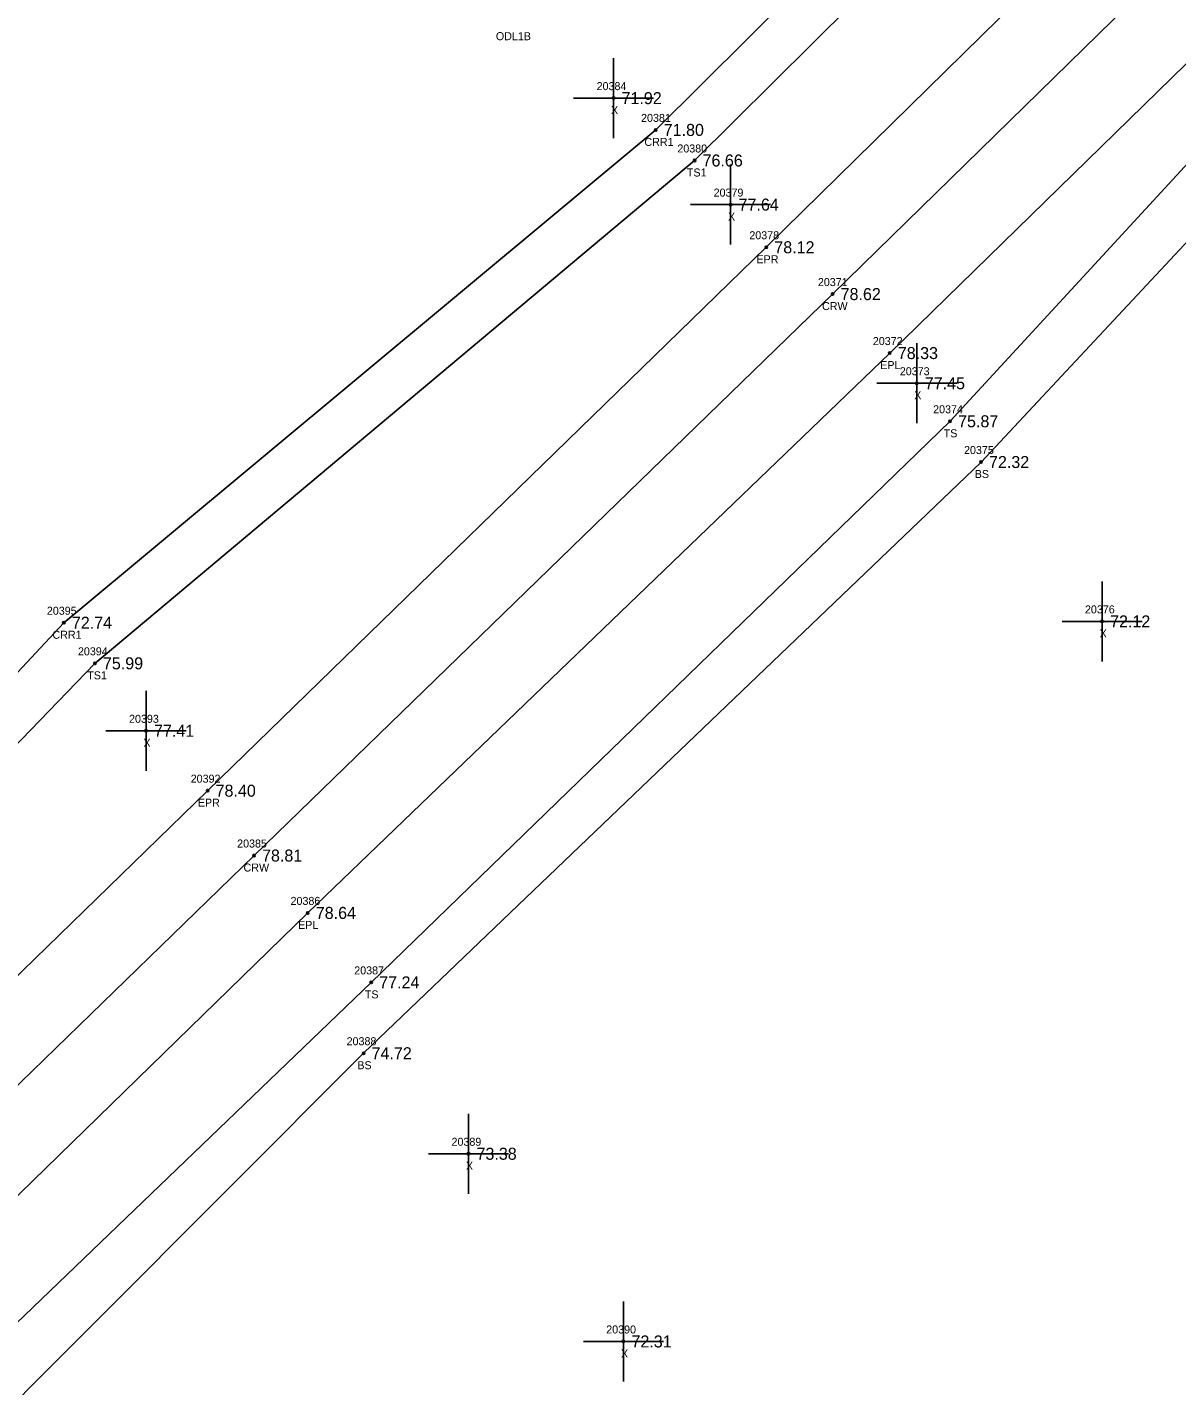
# Model space of a CAD drawing. Extents: x 2505300 to 2506184, y 912965 to 913825.
# Drawn here: x 2505409.2 to 2505552.8, y 913054.5 to 913224.2 of the extents above; entities that cross this region are included whole.
import ezdxf

# ---------------------------------------------------------------- set-up
doc = ezdxf.new("R2010")
doc.units = 0
for name, color, linetype in [('RD_DTM_BkLn1', 7, 'Continuous'), ('RD_DTM_BkLn2', 7, 'Continuous'), ('RD_DTM_BkLn_txCode', 7, 'Continuous'), ('RD_EX_H2O', 7, 'Continuous'), ('RD_EX_H2O_txCode', 7, 'Continuous'), ('RD_EX_Misc', 7, 'Continuous'), ('RD_EX_Misc_txCode', 7, 'Continuous'), ('RD_EX_Road', 7, 'Continuous'), ('RD_EX_Road_txCode', 7, 'Continuous'), ('RD_EX_TX_H2O_ELEV', 7, 'Continuous'), ('RD_EX_TX_Misc_ELEV', 7, 'Continuous'), ('RD_EX_TX_Road_ELEV', 7, 'Continuous'), ('RD_HC_Survey_ELEV', 7, 'Continuous'), ('RD_HC_Survey_txCode', 7, 'Continuous'), ('RD_SMD_Locator', 7, 'Continuous')]:
    doc.layers.add(name, color=color, linetype=linetype)

msp = doc.modelspace()

# ---------------------------------------------------------------- linework, layer by layer
at = {"layer": 'RD_DTM_BkLn1'}
msp.add_lwpolyline([(2505767.92, 913463.52), (2505733.49, 913421.6), (2505698.21, 913380.67), (2505657.08, 913336.16), (2505615.28, 913294.08), (2505578.04, 913257.66), (2505509.81, 913190.87), (2505437.56, 913120.73), (2505363.23, 913048.54)], dxfattribs=at)
at = {"layer": 'RD_DTM_BkLn2'}
for points in [[(2505753.71, 913473.94), (2505744.94, 913478.08), (2505723.86, 913460.1), (2505705.31, 913435.28), (2505675.97, 913399.31), (2505635.15, 913352.85), (2505596.03, 913310.85), (2505561.37, 913275.87), (2505492.57, 913207.56), (2505417.69, 913144.74), (2505344.31, 913068.67)], [(2505608.57, 913197.02), (2505580.09, 913207.47), (2505555.7, 913208.91), (2505524.48, 913174.98), (2505452.19, 913104.88), (2505378.2, 913033.83)], [(2505606.77, 913192.45), (2505577.32, 913200.72), (2505558.46, 913202.1), (2505528.34, 913169.89), (2505451.24, 913096.03), (2505383.47, 913028.12)]]:
    msp.add_lwpolyline(points, dxfattribs=at)
at = {"layer": 'RD_EX_H2O'}
msp.add_lwpolyline([(2505789.47, 913464.31), (2505758.18, 913486.1), (2505736.66, 913480.49), (2505719.32, 913463.86), (2505699.9, 913439.21), (2505669.03, 913402.75), (2505628.5, 913357.9), (2505593, 913316.39), (2505556.58, 913279.8), (2505487.72, 913211.38), (2505413.81, 913149.81), (2505341.31, 913072.1)], dxfattribs=at)
at = {"layer": 'RD_EX_Misc'}
for p, q in [((2505482.45, 913210.35), (2505482.45, 913220.35)), ((2505477.45, 913215.35), (2505487.45, 913215.35)), ((2505497.07, 913197.05), (2505497.07, 913207.05)), ((2505492.07, 913202.05), (2505502.07, 913202.05)), ((2505520.32, 913174.73), (2505520.32, 913184.73)), ((2505515.32, 913179.73), (2505525.32, 913179.73)), ((2505543.46, 913144.98), (2505543.46, 913154.98)), ((2505538.46, 913149.98), (2505548.46, 913149.98)), ((2505424.07, 913131.31), (2505424.07, 913141.31)), ((2505419.07, 913136.31), (2505429.07, 913136.31)), ((2505464.34, 913078.47), (2505464.34, 913088.47)), ((2505459.34, 913083.47), (2505469.34, 913083.47)), ((2505483.69, 913055.02), (2505483.69, 913065.02)), ((2505478.69, 913060.02), (2505488.69, 913060.02))]:
    msp.add_line(p, q, dxfattribs=at)
at = {"layer": 'RD_EX_Road'}
for points in [[(2505758.23, 913470.96), (2505754.11, 913462.85), (2505725.4, 913427.85), (2505690.77, 913387.11), (2505650.25, 913343.36), (2505607.72, 913300.12), (2505570.97, 913264.99), (2505501.53, 913196.72), (2505431.76, 913128.83), (2505356.25, 913055.37)], [(2505777.56, 913455.88), (2505770.31, 913449.85), (2505741, 913414.45), (2505705.55, 913374.27), (2505664.83, 913329.82), (2505624.02, 913288.23), (2505585.62, 913250.63), (2505516.95, 913183.5), (2505444.27, 913113.56), (2505370.6, 913041.78)]]:
    msp.add_lwpolyline(points, dxfattribs=at)
at = {"layer": 'RD_SMD_Locator'}
for centre in [(2505482.45, 913215.35), (2505487.72, 913211.38), (2505492.57, 913207.56), (2505497.07, 913202.05), (2505501.53, 913196.72), (2505509.81, 913190.87), (2505516.95, 913183.5), (2505520.32, 913179.73), (2505524.48, 913174.98), (2505528.34, 913169.89), (2505413.81, 913149.81), (2505543.46, 913149.98), (2505417.69, 913144.74), (2505424.07, 913136.31), (2505431.76, 913128.83), (2505437.56, 913120.73), (2505444.27, 913113.56), (2505452.19, 913104.88), (2505451.24, 913096.03), (2505464.34, 913083.47), (2505483.69, 913060.02)]:
    msp.add_circle(centre, 0.15, dxfattribs=at)

# ---------------------------------------------------------------- texts
at = {"layer": 'RD_DTM_BkLn_txCode'}
for s, p in [('20380', (2505490.42, 913208.56)), ('TS1', (2505491.61, 913205.56)), ('20374', (2505522.36, 913175.98)), ('TS', (2505523.68, 913172.98)), ('20375', (2505526.22, 913170.89)), ('BS', (2505527.56, 913167.89)), ('20394', (2505415.57, 913145.74)), ('TS1', (2505416.73, 913142.74)), ('20387', (2505450.07, 913105.88)), ('TS', (2505451.39, 913102.88)), ('20388', (2505449.12, 913097.03)), ('BS', (2505450.46, 913094.03))]:
    msp.add_text(s, height=1, dxfattribs=at).set_placement(p)
at = {"layer": 'RD_EX_H2O_txCode'}
for s, p in [('ODL1B', (2505467.76, 913222.59)), ('20381', (2505485.89, 913212.38)), ('CRR1', (2505486.31, 913209.38)), ('20395', (2505411.69, 913150.81)), ('CRR1', (2505412.39, 913147.81))]:
    msp.add_text(s, height=1, dxfattribs=at).set_placement(p)
at = {"layer": 'RD_EX_Misc_txCode'}
for s, p in [('20384', (2505480.34, 913216.35)), ('X', (2505482.14, 913213.35)), ('20379', (2505494.95, 913203.05)), ('X', (2505496.75, 913200.05)), ('20373', (2505518.2, 913180.73)), ('X', (2505520, 913177.73)), ('20376', (2505541.32, 913150.98)), ('X', (2505543.15, 913147.98)), ('20393', (2505421.95, 913137.31)), ('X', (2505423.75, 913134.31)), ('20389', (2505462.22, 913084.47)), ('X', (2505464.02, 913081.47)), ('20390', (2505481.54, 913061.02)), ('X', (2505483.38, 913058.02))]:
    msp.add_text(s, height=1, dxfattribs=at).set_placement(p)
at = {"layer": 'RD_EX_Road_txCode'}
for s, p in [('20378', (2505499.41, 913197.72)), ('EPR', (2505500.3, 913194.72)), ('20372', (2505514.83, 913184.5)), ('EPL', (2505515.75, 913181.5)), ('20392', (2505429.65, 913129.83)), ('EPR', (2505430.54, 913126.83)), ('20386', (2505442.12, 913114.56)), ('EPL', (2505443.06, 913111.56))]:
    msp.add_text(s, height=1, dxfattribs=at).set_placement(p)
at = {"layer": 'RD_EX_TX_H2O_ELEV'}
for s, p in [('71.80', (2505488.72, 913210.63)), ('72.74', (2505414.81, 913149.06))]:
    msp.add_text(s, height=1.5, dxfattribs=at).set_placement(p)
at = {"layer": 'RD_EX_TX_Misc_ELEV'}
for s, p in [('71.92', (2505483.45, 913214.6)), ('76.66', (2505493.57, 913206.81)), ('77.64', (2505498.07, 913201.3)), ('77.45', (2505521.32, 913178.98)), ('75.87', (2505525.48, 913174.23)), ('72.32', (2505529.34, 913169.14)), ('72.12', (2505544.46, 913149.23)), ('75.99', (2505418.69, 913143.99)), ('77.41', (2505425.07, 913135.56)), ('77.24', (2505453.19, 913104.13)), ('74.72', (2505452.24, 913095.28)), ('73.38', (2505465.34, 913082.72)), ('72.31', (2505484.69, 913059.27))]:
    msp.add_text(s, height=1.5, dxfattribs=at).set_placement(p)
at = {"layer": 'RD_EX_TX_Road_ELEV'}
for s, p in [('78.12', (2505502.53, 913195.97)), ('78.33', (2505517.95, 913182.75)), ('78.40', (2505432.76, 913128.08)), ('78.64', (2505445.27, 913112.81))]:
    msp.add_text(s, height=1.5, dxfattribs=at).set_placement(p)
at = {"layer": 'RD_HC_Survey_ELEV'}
for s, p in [('78.62', (2505510.81, 913190.12)), ('78.81', (2505438.56, 913119.98))]:
    msp.add_text(s, height=1.5, dxfattribs=at).set_placement(p)
at = {"layer": 'RD_HC_Survey_txCode'}
for s, p in [('20371', (2505507.97, 913191.87)), ('CRW', (2505508.49, 913188.87)), ('20385', (2505435.45, 913121.73)), ('CRW', (2505436.25, 913118.73))]:
    msp.add_text(s, height=1, dxfattribs=at).set_placement(p)

doc.saveas('drawing.dxf')
